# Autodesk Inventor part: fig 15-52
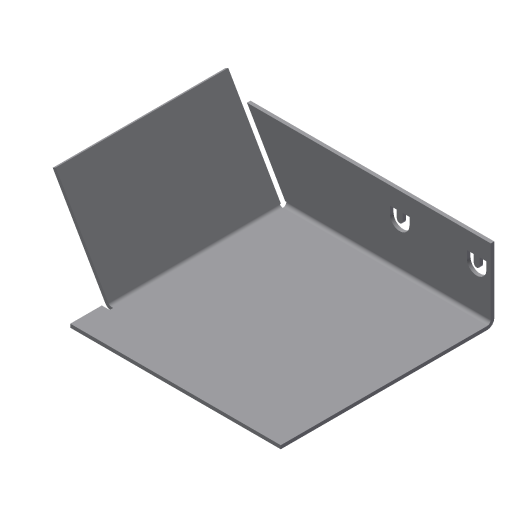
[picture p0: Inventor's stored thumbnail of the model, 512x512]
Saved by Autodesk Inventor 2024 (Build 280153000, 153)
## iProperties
Shininess: 77.0
Angle Display Precision: 2
Document Length Units: 11269
Document Angle Units: 11279
Document Time Units: 11290
Document Mass Units: 11283
Document Length Units Precision: 3
Document Angle Units Precision: 2
Created: 2002-04
Part Number: fig 15-52
Document SubType Name: Sheet Metal
Density: 1 g/cm^3
Sheet Metal Rule: Default
Material: Generic
Appearance: Default
Density: 0.0
Volumn: 0.0
Area: 0.0
PropertySet Name: Model Information
Control State: 0
Master: False
Checked Out: False
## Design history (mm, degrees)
node "Face1"
  sketch "Sketch1"
    geometry: L1 (12.647, 25.882)-(12.647, -14.118); L2 (12.647, -14.118)-(-17.353, -14.118); L3 (-17.353, -14.118)-(-17.353, 15.882); L4 (-17.353, 15.882)-(-2.353, 15.882); L5 (-2.353, 15.882)-(-2.353, 25.882); L6 (-2.353, 25.882)-(12.647, 25.882); 1 further point
    constraints: 12 end point, 4 parallel, 1 perpendicular
    dimensions: "d5" = 30 distance of L2.end L3.end; "d6" = 10 distance of L4.end L5.end; "d7" = 15 distance of L3.end L4.end; "d25" = 15 distance of L5.end L1.start
sketch "Sketch3"
  geometry: L1 (10, -15)-(10, 0)
  constraints: 2 end point
feature "Fold3" sketch "Sketch3" dims "d26" = 0.5 (= BendRadius), "d27" = 90 deg, "d28" = 0.5 (= BendRadius), "d96" = 0.5 (= BendReliefWidth), "d97" = 0.25 (= BendReliefDepth), "d98" = 1 (= MinimumRemnant), "d112" = 0.5 (= Thickness), "SeamGap" = 0.01
node "Flange2"
sketch "Sketch6"
  geometry: L1 (-6.914, 3.413)-(-5.843, 3.413); L2 (-5.843, 0.624)-(-6.914, 0.624); L3 (-6.914, 2.432)-(-5.843, 2.432); L4 (-5.843, 1.605)-(-6.914, 1.605); L5 (-6.914, 0.624)-(-6.914, 1.605); L6 (-6.914, 2.432)-(-6.914, 3.413); L7 (-6.914, 12.568)-(-6.914, 11.587); L8 (-6.914, 14.376)-(-6.914, 13.395); L9 (-6.914, 11.587)-(-5.843, 11.587); L10 (-5.843, 14.376)-(-6.914, 14.376); L11 (-6.914, 12.568)-(-5.843, 12.568); L12 (-5.843, 13.395)-(-6.914, 13.395); A1 r 1.394 centre (-5.843, 2.018) between (-5.843, 0.624) and (-5.843, 3.413); A2 r 0.413 centre (-5.843, 2.018) between (-5.843, 1.605) and (-5.843, 2.432); A3 r 1.394 centre (-5.843, 12.982) between (-5.843, 11.587) and (-5.843, 14.376); A4 r 0.413 centre (-5.843, 12.982) between (-5.843, 12.568) and (-5.843, 13.395)
  constraints: 24 end point, 8 point on circle, 4 centre point, 3 equal length, 1 perpendicular
cut "Cut1" sketch "Sketch6" dims "d49" = 0.5 (= Thickness), "d50" = 0
feature "Corner3" dims "d107" = 2 (= CornerReliefSize), "d108" = 0.5 (= BendRadius), "d109" = 0.5 (= GapSize), "d110" = 0, "d111" = 10, "d112" = 0.5 (= Thickness)
body "Solid1"
face "Plate1" dims "d112" = 0.5 (= Thickness)
sketch "Sketch5"
  geometry: L1 (20, 0)-(5, 0); L2 (5, 0)-(5, 15); L3 (5, 15)-(20, 15); L4 (20, 15)-(20, 0)
  constraints: 8 end point
face "Plate6" dims "d35" = 10, "d36" = 5, "d38" = 15, "d39" = 60 deg, "d40" = 0.5 (= BendRadius), "d112" = 0.5 (= Thickness), "MinimumRemnant" = 1 (= 2 x Thickness), "BendReliefWidth" = 0.5 (= Thickness)
bend "Bend5" dims "d38" = 15, "d39" = 60 deg, "d40" = 0.5 (= BendRadius), "d99" = 0.5 (= BendReliefWidth), "d100" = 0.25 (= BendReliefDepth), "d101" = 1 (= MinimumRemnant), "d112" = 0.5 (= Thickness), "SeamGap" = 0.01, "MinimumRemnant" = 1 (= 2 x Thickness), "BendReliefWidth" = 0.5 (= Thickness), "TransitionRadius" = 0.5 (= BendRadius)
other parameters: "Thickness" = 0.5, "BendRadius" = 0.5 (= Thickness), "BendReliefDepth" = 0.25 (= 0.5 x Thickness), "CornerReliefSize" = 2 (= 4 x Thickness), "d0" = 0.5 (= BendRadius), "d13" = 0.5 (= BendRadius), "d31" = 0.5 (= BendRadius), "d37" = 0.5 (= BendRadius), "JacobiRadiusSize" = 0.5 (= Thickness), "GapSize" = 0.5 (= Thickness)
